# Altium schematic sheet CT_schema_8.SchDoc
size 277 x 170 mm
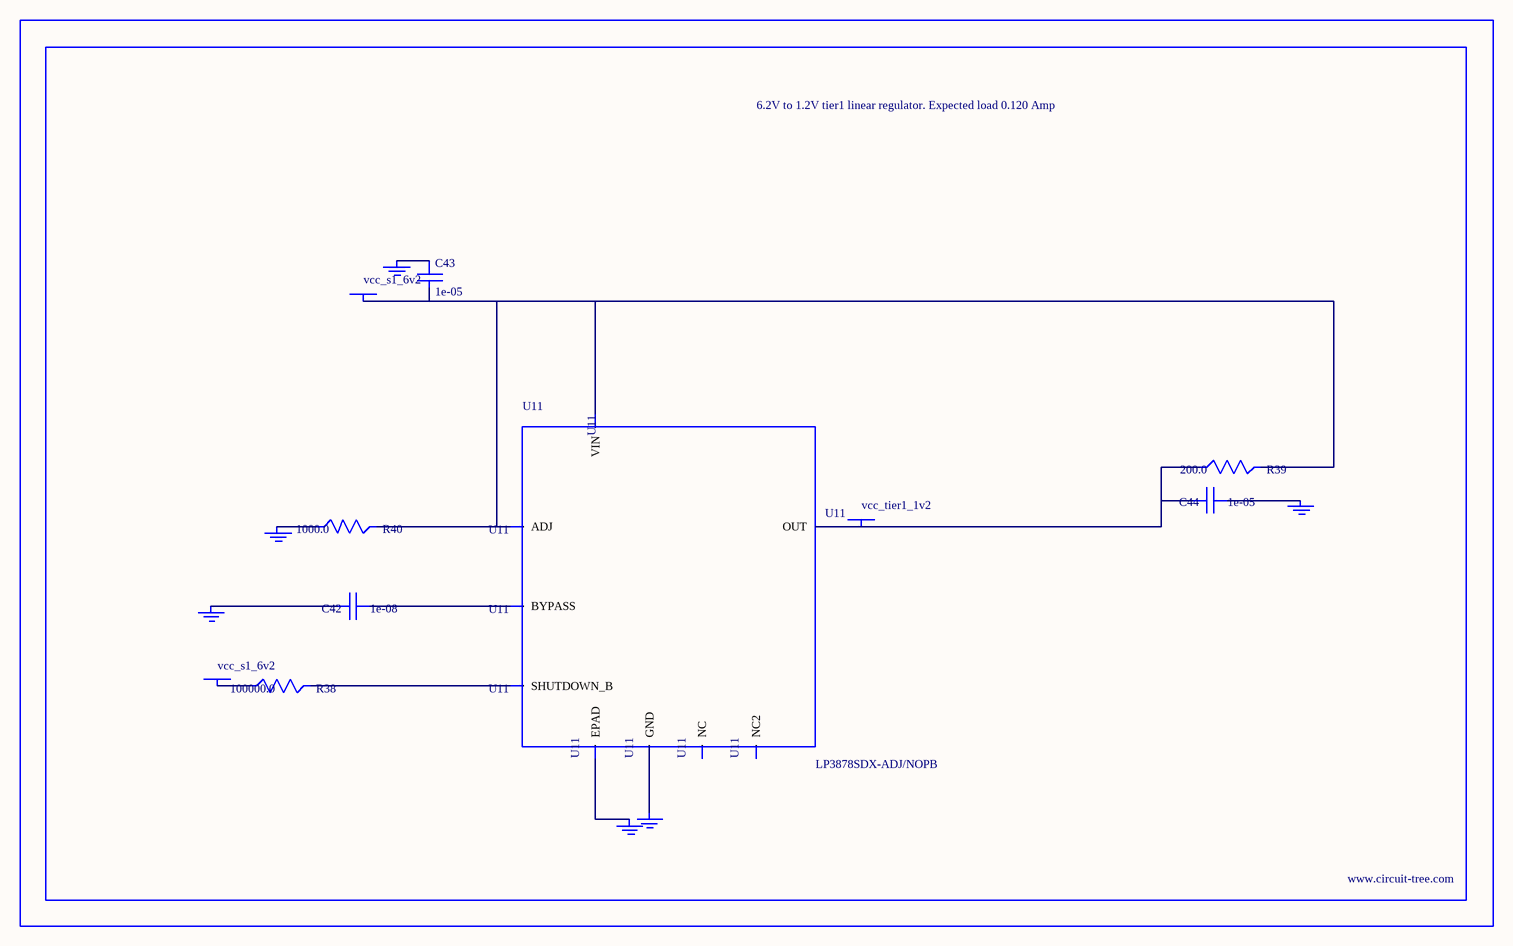
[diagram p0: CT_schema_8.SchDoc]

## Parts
BORDER7  (no value)
C42  1e-08  [C0402]
C43  1e-05  [C1206]
C44  1e-05  [C0805]
GND_INSTANCE_7_0  (no value)
GND_INSTANCE_7_1  (no value)
GND_INSTANCE_7_2  (no value)
GND_INSTANCE_7_3  (no value)
GND_INSTANCE_7_4  (no value)
GND_INSTANCE_7_5  (no value)
POWER_INSTANCE_7_0  vcc_s1_6v2
POWER_INSTANCE_7_1  vcc_s1_6v2
POWER_INSTANCE_7_2  vcc_tier1_1v2
R38  100000.0  [R0603]
R39  200.0  [R0603]
R40  1000.0  [R0603]
U11  LP3878SDX-ADJ/NOPB  [WSON-8]

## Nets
NetC42_1: C42.1 U11.1(BYPASS)
NetC42_2: C42.2 GND_INSTANCE_7_0.0(GND)
NetC43_1: C43.1 GND_INSTANCE_7_1.0(GND)
NetC43_2: C43.2 POWER_INSTANCE_7_0.0(PWR) R39.2 R40.2 U11.4(VIN) U11.6(ADJ)
NetC44_1: C44.1 GND_INSTANCE_7_2.0(GND)
NetC44_2: C44.2 POWER_INSTANCE_7_2.0(PWR) R39.1 U11.5(OUT)
NetGND_INSTANCE_7_3_0: GND_INSTANCE_7_3.0(GND) R40.1
NetGND_INSTANCE_7_4_0: GND_INSTANCE_7_4.0(GND) U11.PAD(EPAD)
NetGND_INSTANCE_7_5_0: GND_INSTANCE_7_5.0(GND) U11.3(GND)
NetPOWER_INSTANCE_7_1_0: POWER_INSTANCE_7_1.0(PWR) R38.1
NetR38_2: R38.2 U11.8(SHUTDOWN_B)

Not connected (* = marked no-connect by the designer): U11 2(NC) 7(NC2)

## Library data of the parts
BORDER7 = BORDER_PAGE7
C42 = C0402C103K3RAC
C43 = C1206C106K3RACTU
C44 = GRM219R60J106ME19D
GND_INSTANCE_7_0-GND_INSTANCE_7_5 = GND
POWER_INSTANCE_7_0-POWER_INSTANCE_7_2 = PWR
R38 = RC0603JR-07100KL
R39 = RC0603JR-07200RL
R40 = RC0603JR-071KL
